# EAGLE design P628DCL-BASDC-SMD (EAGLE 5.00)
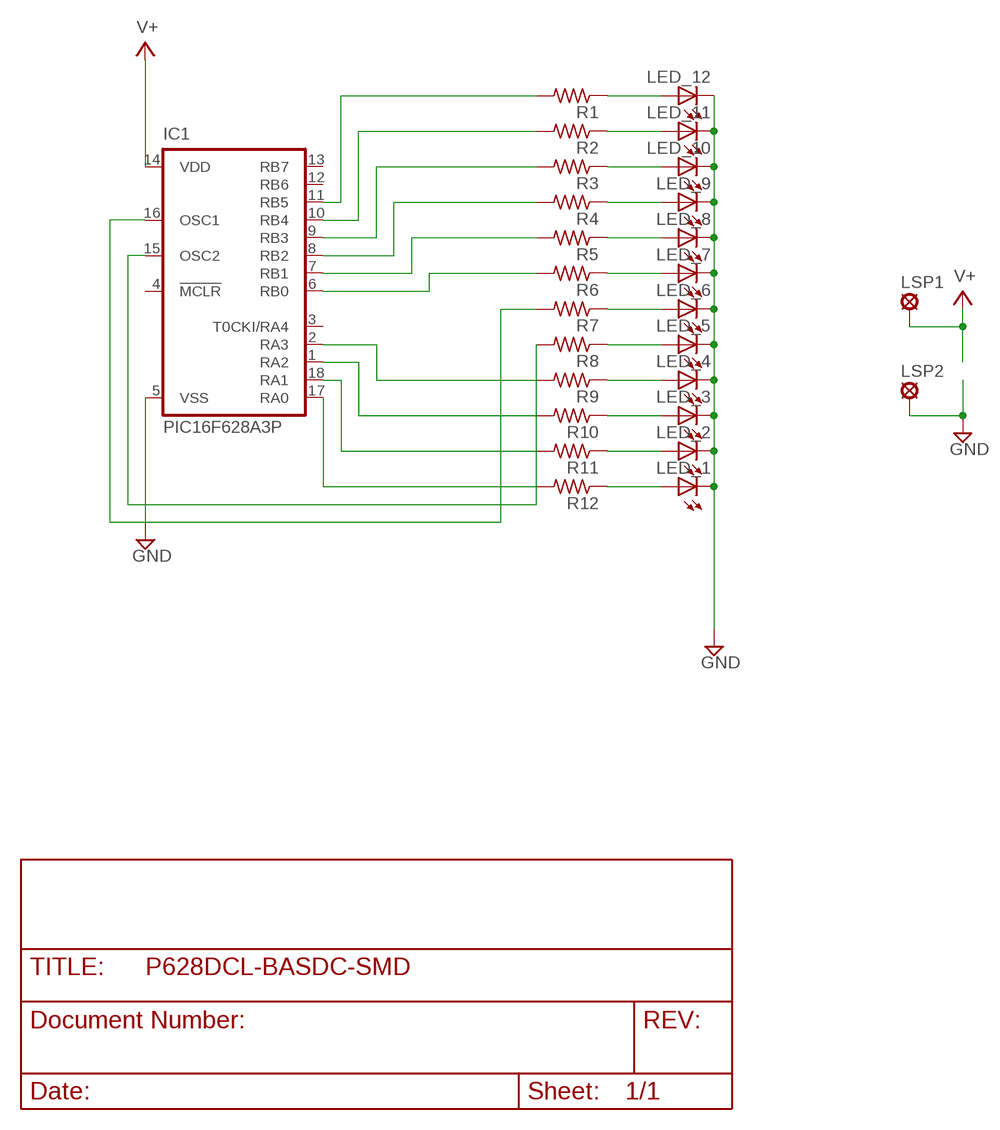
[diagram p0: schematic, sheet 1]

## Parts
IC1  PIC16F628A3P  [DIL18]
LED_1  LEDSMT1206  [1206]
LED_2  LEDSMT1206  [1206]
LED_3  LEDSMT1206  [1206]
LED_4  LEDSMT1206  [1206]
LED_5  LEDSMT1206  [1206]
LED_6  LEDSMT1206  [1206]
LED_7  LEDSMT1206  [1206]
LED_8  LEDSMT1206  [1206]
LED_9  LEDSMT1206  [1206]
LED_10  LEDSMT1206  [1206]
LED_11  LEDSMT1206  [1206]
LED_12  LEDSMT1206  [1206]
LSP1  LSP10  [LSP10]
LSP2  LSP10  [LSP10]
R1  R-US_M1206  [M1206]
R2  R-US_M1206  [M1206]
R3  R-US_M1206  [M1206]
R4  R-US_R1206  [R1206]
R5  R-US_M1206  [M1206]
R6  R-US_M1206  [M1206]
R7  R-US_M1206  [M1206]
R8  R-US_M1206  [M1206]
R9  R-US_M1206  [M1206]
R10  R-US_M1206  [M1206]
R11  R-US_M1206  [M1206]
R12  R-US_M1206  [M1206]

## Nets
GND: IC1.5(VSS) LED_1.C LED_2.C LED_3.C LED_4.C LED_5.C LED_6.C LED_7.C LED_8.C LED_9.C LED_10.C LED_11.C LED_12.C LSP2.MP
N$1: IC1.15(OSC2) R8.2
N$2: LED_12.A R1.1
N$3: LED_11.A R2.1
N$4: LED_10.A R3.1
N$5: LED_9.A R4.1
N$6: LED_8.A R5.1
N$7: LED_7.A R6.1
N$8: LED_6.A R7.1
N$9: LED_5.A R8.1
N$10: LED_4.A R9.1
N$11: LED_3.A R10.1
N$12: LED_2.A R11.1
N$13: LED_1.A R12.1
N$14: IC1.16(OSC1) R7.2
N$17: IC1.17(RA0) R12.2
N$18: IC1.18(RA1) R11.2
N$19: IC1.1(RA2) R10.2
N$20: IC1.2(RA3) R9.2
N$22: IC1.10(RB4) R2.2
N$23: IC1.9(RB3) R3.2
N$24: IC1.8(RB2) R4.2
N$25: IC1.7(RB1) R5.2
N$26: IC1.6(RB0) R6.2
N$29: IC1.11(RB5) R1.2
V+: IC1.14(VDD) LSP1.MP
Unconnected: IC1.3(T0CKI/RA4) IC1.4(!MCLR) IC1.12(RB6) IC1.13(RB7)

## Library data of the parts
IC1 = microchip:PIC16F628A: MICROCONTROLLER 8-Bit PIC16F8X Family - CMOS Flash/EEPROM Pin Compatible : PIC16F83, PIC16CR83, PIC16F84A, PIC16CR84 see also PIC16C*
LED_1-LED_12 = led:LED: LED
LSP1 LSP2 = solpad:LSP10: SOLDER PAD
R1-R12 = rcl:R-US_: RESISTOR, American symbol

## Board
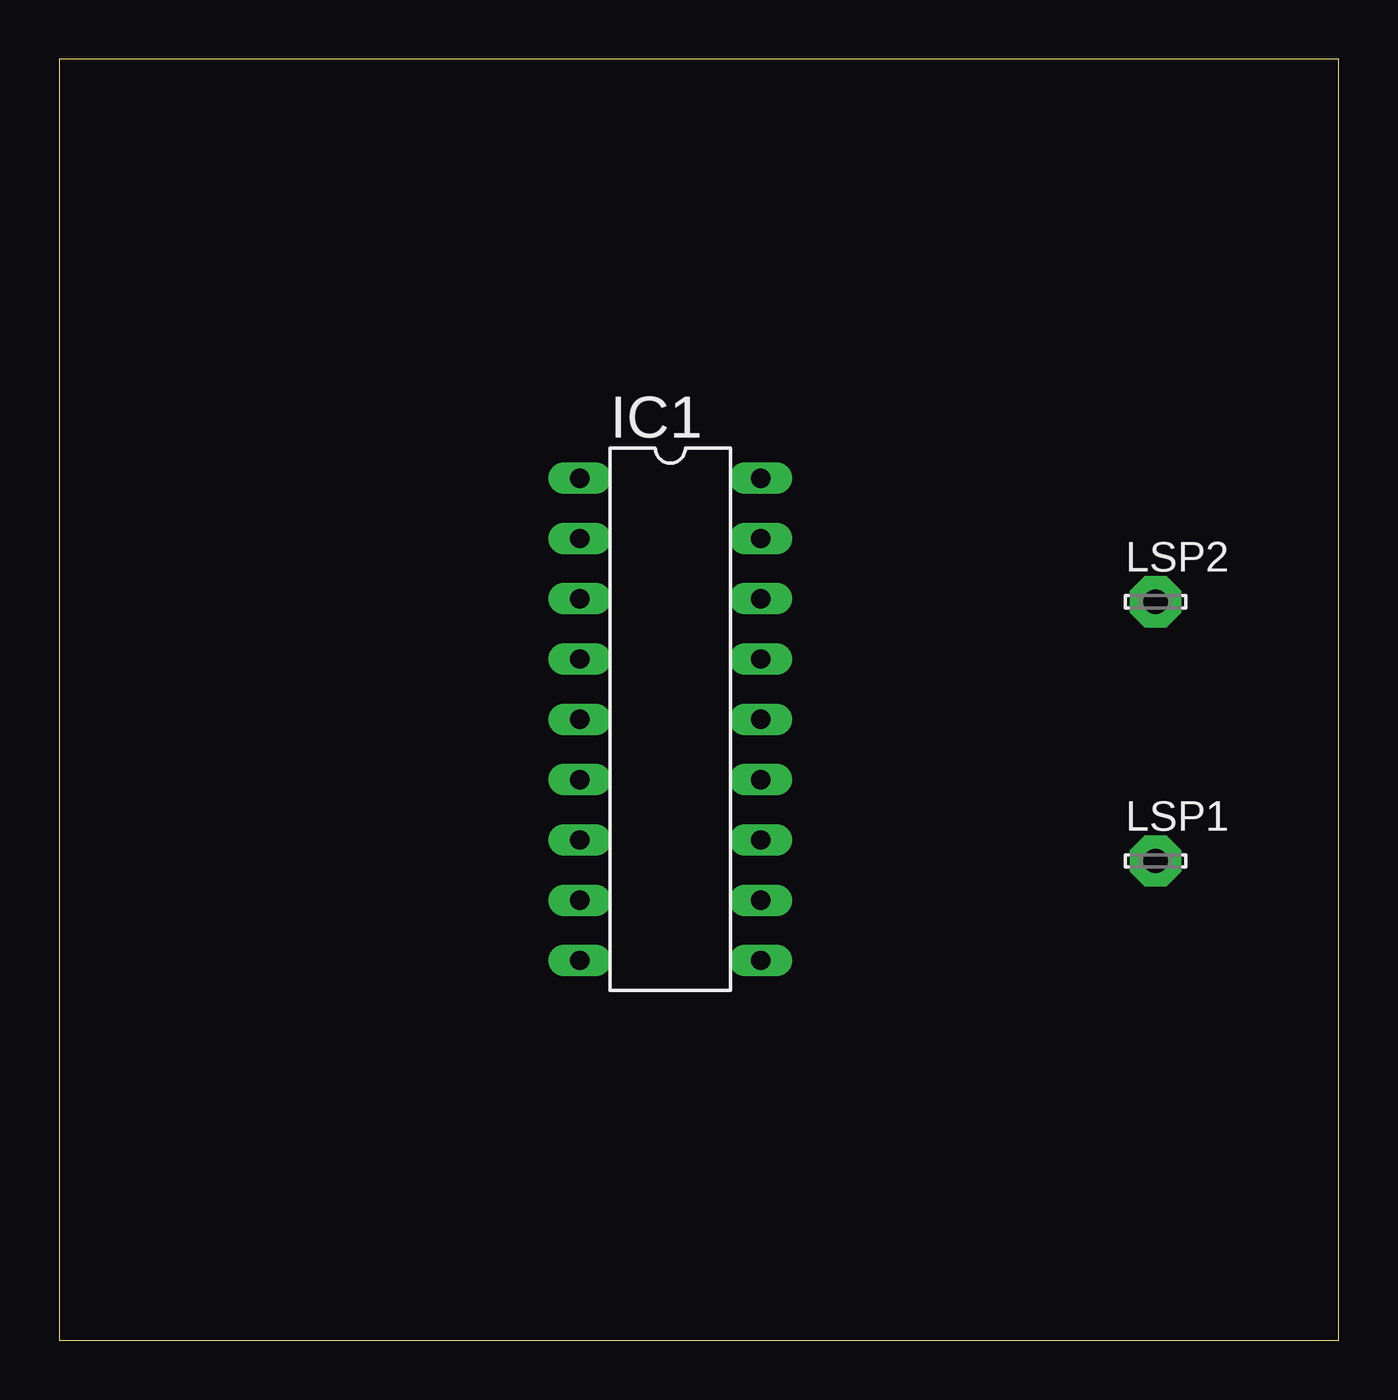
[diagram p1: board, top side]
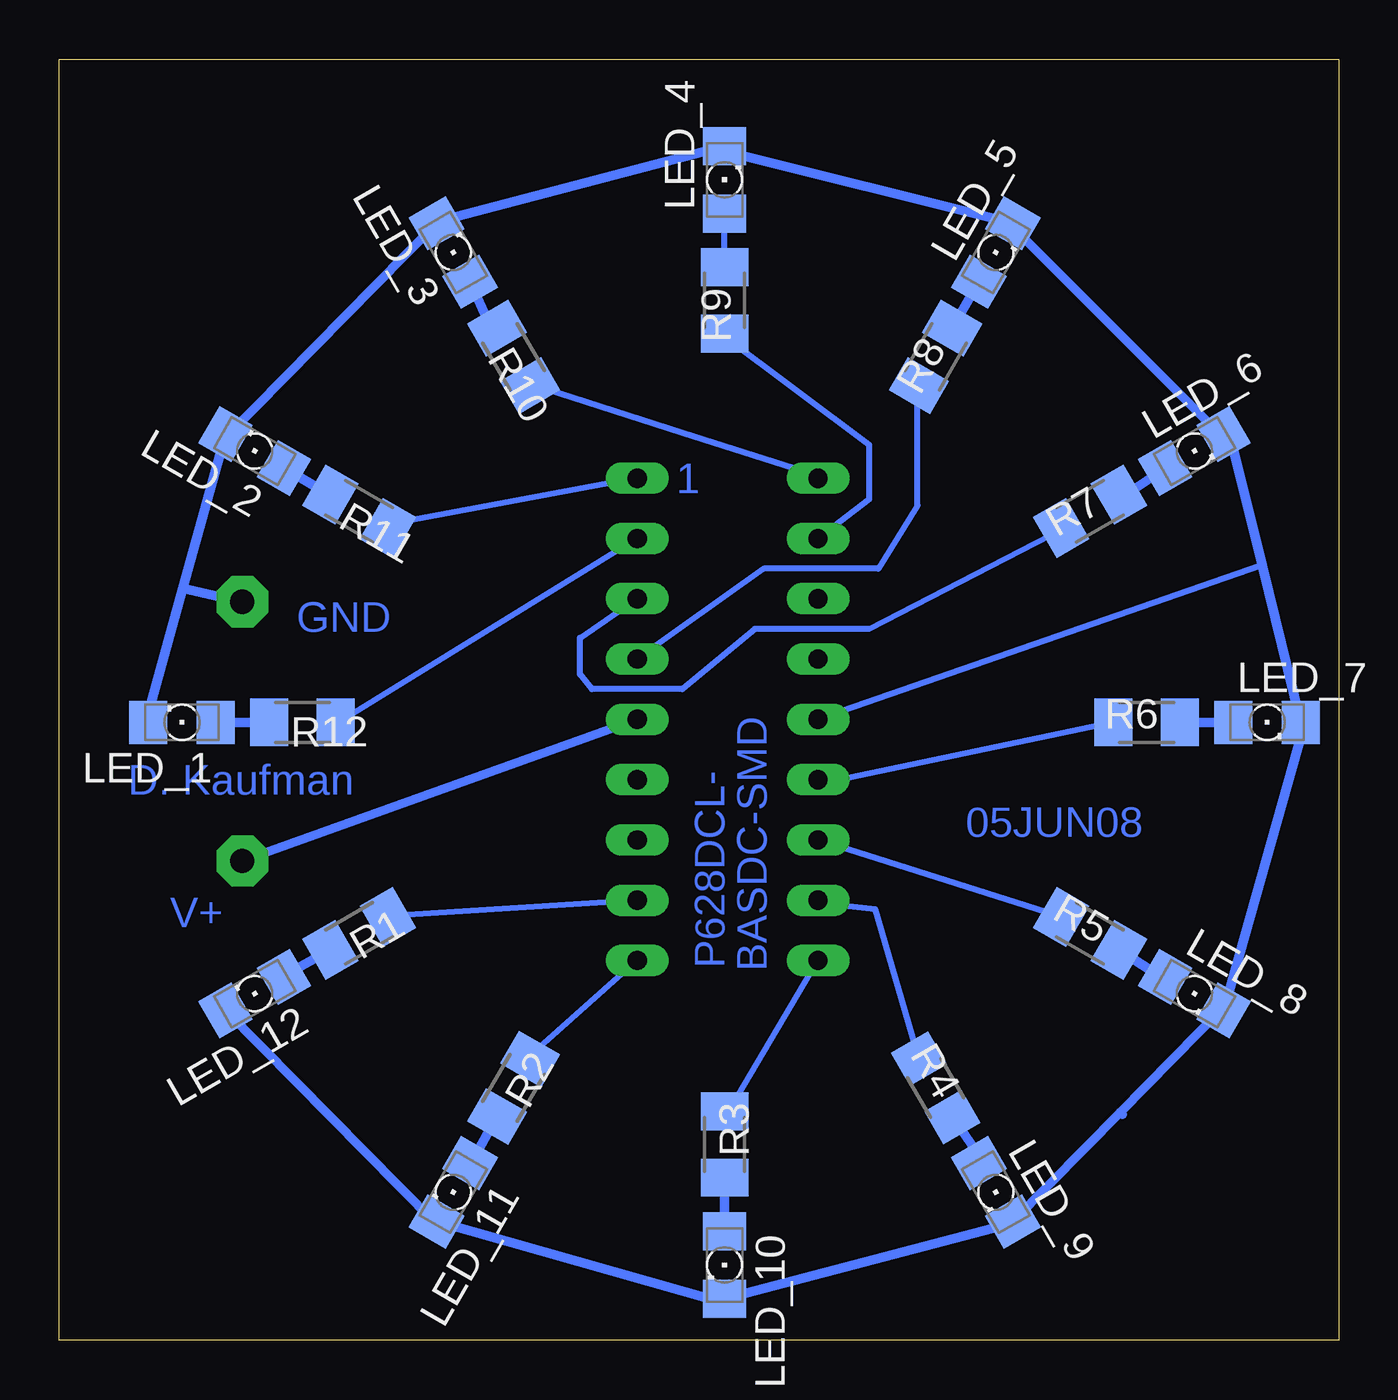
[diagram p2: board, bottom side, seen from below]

Size 53.9 x 53.97 mm. Coordinates in mm from the lower left corner, seen from the top.
Outline: 0,0 53.9,0 53.9,53.97 0,53.97 0,0
Copper layers (1*16): Top 0.035mm / dielectric 1.5mm / Bottom 0.035mm
Design rules "polywide": minimum track width 10mil, minimum drill 24mil, track to track 50mil, track to pad 50mil, pad to pad 50mil, via to via 50mil, smd to smd 8mil, copper to edge 40mil, drill to drill 50mil, minimum pad ring 10mil, minimum via ring 8mil, stop-mask expansion 4mil, vias tented up to drill 0mil, thermal gap 10mil

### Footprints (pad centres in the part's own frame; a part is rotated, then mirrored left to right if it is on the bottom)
DIL18 = drill 0.813 long: 1 -10.16,-3.81; 2 -7.62,-3.81; 3 -5.08,-3.81; 4 -2.54,-3.81; 5 0,-3.81; 6 2.54,-3.81; 7 5.08,-3.81; 8 7.62,-3.81; 9 10.16,-3.81; 10 10.16,3.81; 11 7.62,3.81; 12 5.08,3.81; 13 2.54,3.81; 14 0,3.81; 15 -2.54,3.81; 16 -5.08,3.81; 17 -7.62,3.81; 18 -10.16,3.81
1206 = smd 1.6 x 1.803: A -1.422,0; C 1.422,0
LSP10 = drill 1.016 pad 2.159 octagon: MP 0,0
M1206 = smd 1.6 x 2: 1 -1.4,0; 2 1.4,0
R1206 = smd 1.6 x 1.803: 1 -1.422,0; 2 1.422,0

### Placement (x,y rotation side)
IC1  25.74,26.16 270 top
LED_1  48.73,26.03 180 bottom
LED_2  45.67,37.46 150 bottom
LED_3  37.3,45.83 120 bottom
LED_4  25.87,48.89 90 bottom
LED_5  14.44,45.83 60 bottom
LED_6  6.07,37.46 30 bottom
LED_7  3.01,26.03 0 bottom
LED_8  6.07,14.6 330 bottom
LED_9  14.44,6.23 300 bottom
LED_10  25.87,3.17 270 bottom
LED_11  37.3,6.23 240 bottom
LED_12  45.67,14.6 210 bottom
LSP1  46.19,20.19 0 top
LSP2  46.19,31.11 0 top
R1  41.27,17.14 30 bottom
R2  34.76,10.63 60 bottom
R3  25.87,8.25 90 bottom
R4  16.98,10.63 120 bottom
R5  10.47,17.14 150 bottom
R6  8.09,26.03 180 bottom
R7  10.47,34.92 210 bottom
R8  16.98,41.43 240 bottom
R9  25.87,43.81 270 bottom
R10  34.76,41.43 300 bottom
R11  41.27,34.92 330 bottom
R12  43.65,26.03 0 bottom

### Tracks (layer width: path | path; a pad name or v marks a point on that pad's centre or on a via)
GND
  Bottom 0.254: 3.26,32.63 IC1.5 | 13.17,46.35 LED_5.C | LED_6.C 5.55,38.73
  Bottom 0.406: LED_5.C 26.12,50.16 LED_4.C 38.06,47.11 LED_3.C 46.95,37.97 LED_2.C 48.69,31.68 | LED_1.C 50.25,26.03 48.69,31.68 | LED_12.C 46.95,13.84 | LED_12.C 38.06,4.95 LED_11.C 26.12,1.65 LED_10.C 13.68,4.95 LED_9.C 9.2,9.61 | 9.2,9.61 4.79,14.09 LED_8.C 1.49,25.78 LED_7.C 3.22,32.65 | LED_6.C 4.53,37.97 3.22,32.65 | 3.22,32.65 3.26,32.63 | 9.2,9.61 9.11,9.52 | 48.69,31.68 48.48,31.62 LSP2.MP | LED_12.C 46.95,13.58 | 5.55,38.73 13.17,46.35
N$1
  Bottom 0.254: IC1.15 24.22,32.51 19.39,32.51 17.74,35.17 17.74,40.25
  Bottom 0.406: 17.74,40.25 R8.2
N$2
  Bottom 0.406: LED_12.A 44.41,15.36 R1.1
N$3
  Bottom 0.406: LED_11.A 36.54,7.49 R2.1
N$4
  Bottom 0.406: 25.87,4.44 LED_10.A R3.1
N$5
  Bottom 0.406: LED_9.A 14.95,7.49 R4.1
N$6
  Bottom 0.406: LED_8.A 7.58,15.36 R5.1
N$7
  Bottom 0.406: LED_7.A R6.1
N$8
  Bottom 0.406: R7.1 8.85,35.68 LED_6.A
N$9
  Bottom 0.406: R8.1 16.47,42.29 LED_5.A
N$10
  Bottom 0.254: 25.87,47.62 LED_4.A R9.1 25.87,45.08
N$11
  Bottom 0.406: R10.1 35.78,42.79 LED_3.A
N$12
  Bottom 0.406: R11.1 42.63,35.68 LED_2.A
N$13
  Bottom 0.406: R12.1 LED_1.A
N$14
  Bottom 0.254: IC1.16 31.97,29.59 31.97,28.06 31.46,27.43 27.65,27.43 24.6,29.97 19.77,29.97 12.15,33.9
  Bottom 0.406: R7.2 11.9,34.16 12.15,33.9
N$17
  Bottom 0.254: IC1.17 42.13,26.03
  Bottom 0.406: 42.13,26.03 R12.2
N$18
  Bottom 0.254: IC1.18 39.84,34.41
  Bottom 0.406: 39.84,34.41 R11.2
N$19
  Bottom 0.254: IC1.1 22.06,36.44 27.65,38.22 34,40.25
  Bottom 0.406: 34,40.25 R10.2
N$20
  Bottom 0.254: IC1.2 19.77,35.43 19.77,37.71 25.87,42.29
  Bottom 0.406: 25.62,42.54 R9.2 25.87,42.29
N$22
  Bottom 0.254: 34.25,11.81 IC1.10
  Bottom 0.406: R2.2 34.25,11.81
N$23
  Bottom 0.254: 25.62,9.77 IC1.9
  Bottom 0.406: 25.62,9.77 R3.2
N$24
  Bottom 0.254: R4.2 19.52,18.16 21.81,18.41
  Bottom 0.406: 21.81,18.41 IC1.8
N$25
  Bottom 0.254: 11.9,17.9 IC1.7
  Bottom 0.406: R5.2 11.9,17.9
N$26
  Bottom 0.254: R6.2 21.55,23.49
  Bottom 0.406: 21.55,23.49 IC1.6
N$29
  Bottom 0.254: IC1.11 39.59,17.9
  Bottom 0.406: 39.59,17.9 R1.2
V+
  Bottom 0.406: IC1.14 LSP1.MP

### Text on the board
Bottom: 1 | GND | BASDC-SMD | P628DCL- | D. Kaufman | 05JUN08 | V+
